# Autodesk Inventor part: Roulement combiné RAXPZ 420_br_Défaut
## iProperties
Shininess: 64.0
Length Units: 11269
Angle Units: 11279
Time Units: 11290
Mass Units: 11283
Length Display Precision: 3
Angle Display Precision: 2
Compacted: True
Part Number: Roulement combiné RAXPZ 420_br_Défaut
Document SubType Name: Modeling
Created: 2006-01
Material: Par défaut
Designer: riri
Density: 0.0
Volumn: 0.0
Area: 0.0
PropertySet Name: Model Information
Control State: 0
Master: False
Checked Out: False
Author: riri
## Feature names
1. Base1
